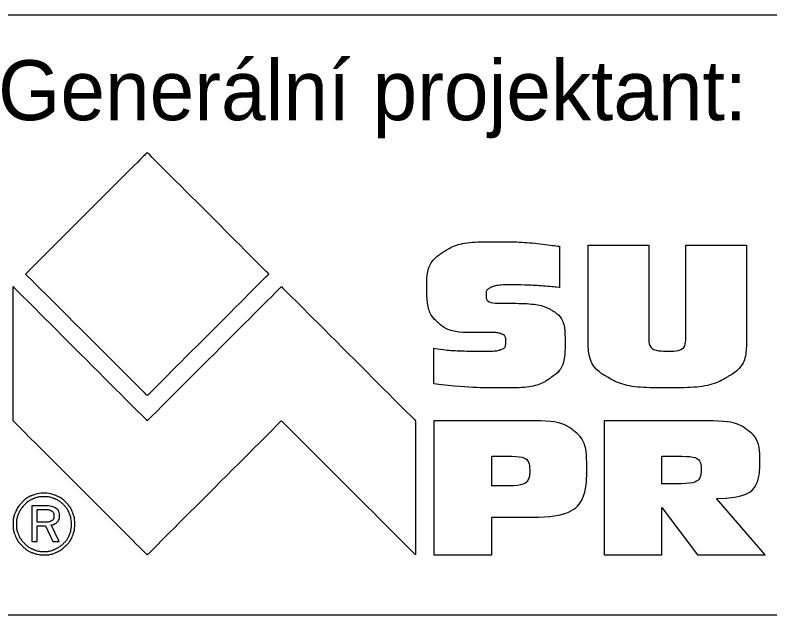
# Model space of a CAD drawing. Extents: x -573127 to 0, y -1197729 to 0.
# Drawn here: x -573104.72 to -573079.55, y -1197649.86 to -1197629.86 of the extents above; entities that cross this region are included whole.
import ezdxf

# ---------------------------------------------------------------- set-up
doc = ezdxf.new("R2010")
doc.units = 0
doc.layers.add('Default', color=7, linetype='Continuous')

msp = doc.modelspace()

# ---------------------------------------------------------------- linework, layer by layer
at = {"layer": 'Default'}
msp.add_lwpolyline([(-573106.787, -1197649.864), (-572926.787, -1197649.858), (-572926.788, -1197629.858), (-573106.788, -1197629.864)], close=True, dxfattribs=at)
msp.add_lwpolyline([(-573106.787, -1197649.864), (-572926.787, -1197649.858), (-572926.788, -1197629.858), (-573106.788, -1197629.864)], close=True, dxfattribs=at)
for points in [[(-573087.412, -1197643.389), (-573090.76, -1197643.389), (-573090.759, -1197647.863), (-573088.825, -1197647.863), (-573088.825, -1197646.607), (-573087.488, -1197646.606)], [(-573081.671, -1197643.389), (-573085.077, -1197643.389), (-573085.077, -1197647.863), (-573083.151, -1197647.863), (-573083.151, -1197646.277), (-573081.965, -1197647.863), (-573079.707, -1197647.863), (-573081.333, -1197645.976)], [(-573088.252, -1197645.561), (-573088.825, -1197645.561), (-573088.825, -1197644.572), (-573088.155, -1197644.572)], [(-573082.508, -1197645.488), (-573083.151, -1197645.488), (-573083.151, -1197644.572), (-573082.484, -1197644.572)], [(-573103.728, -1197646.225), (-573104.163, -1197646.225), (-573104.163, -1197647.41), (-573103.984, -1197647.41), (-573103.984, -1197646.89), (-573103.707, -1197646.89), (-573103.457, -1197647.41), (-573103.253, -1197647.41), (-573103.518, -1197646.864)], [(-573103.762, -1197646.772), (-573103.984, -1197646.772), (-573103.984, -1197646.346), (-573103.762, -1197646.346)]]:
    msp.add_lwpolyline(points, dxfattribs=at)
for points in [[(-573104.368, -1197638.495), (-573104.368, -1197638.495), (-573100.313, -1197634.44), (-573100.313, -1197634.44), (-573100.313, -1197634.44), (-573100.313, -1197634.44), (-573096.258, -1197638.495), (-573096.258, -1197638.495), (-573096.258, -1197638.495), (-573096.258, -1197638.495), (-573100.313, -1197642.55), (-573100.313, -1197642.55), (-573100.313, -1197642.55), (-573100.313, -1197642.55), (-573104.368, -1197638.495), (-573104.368, -1197638.495)], [(-573090.76, -1197642.162), (-573090.032, -1197642.249), (-573089.269, -1197642.293), (-573088.47, -1197642.293), (-573088.47, -1197642.293), (-573087.704, -1197642.293), (-573087.165, -1197642.18), (-573086.853, -1197641.955), (-573086.853, -1197641.955), (-573086.539, -1197641.73), (-573086.381, -1197641.342), (-573086.381, -1197640.79), (-573086.381, -1197640.79), (-573086.381, -1197640.251), (-573086.523, -1197639.891), (-573086.806, -1197639.711), (-573086.806, -1197639.711), (-573087.073, -1197639.55), (-573087.614, -1197639.469), (-573088.43, -1197639.469), (-573088.43, -1197639.469), (-573088.821, -1197639.469), (-573089.017, -1197639.377), (-573089.017, -1197639.192), (-573089.017, -1197639.192), (-573089.017, -1197639.075), (-573088.959, -1197638.99), (-573088.844, -1197638.937), (-573088.844, -1197638.937), (-573088.727, -1197638.884), (-573088.521, -1197638.858), (-573088.229, -1197638.858), (-573088.229, -1197638.858), (-573087.732, -1197638.858), (-573087.187, -1197638.886), (-573086.568, -1197638.943), (-573086.568, -1197638.943), (-573086.568, -1197638.943), (-573086.568, -1197637.571), (-573086.568, -1197637.571), (-573086.568, -1197637.571), (-573087.307, -1197637.467), (-573087.998, -1197637.416), (-573088.668, -1197637.416), (-573088.668, -1197637.416), (-573089.51, -1197637.416), (-573090.108, -1197637.535), (-573090.461, -1197637.775), (-573090.461, -1197637.775), (-573090.814, -1197638.013), (-573090.99, -1197638.393), (-573090.99, -1197638.915), (-573090.99, -1197638.915), (-573090.99, -1197639.494), (-573090.864, -1197639.896), (-573090.612, -1197640.119), (-573090.612, -1197640.119), (-573090.358, -1197640.341), (-573089.935, -1197640.451), (-573089.345, -1197640.446), (-573089.345, -1197640.446), (-573089.345, -1197640.446), (-573088.851, -1197640.446), (-573088.851, -1197640.446), (-573088.851, -1197640.446), (-573088.679, -1197640.446), (-573088.553, -1197640.465), (-573088.473, -1197640.504), (-573088.473, -1197640.504), (-573088.394, -1197640.542), (-573088.355, -1197640.625), (-573088.355, -1197640.752), (-573088.355, -1197640.752), (-573088.355, -1197640.886), (-573088.406, -1197640.972), (-573088.509, -1197641.01), (-573088.509, -1197641.01), (-573088.61, -1197641.048), (-573088.781, -1197641.067), (-573089.021, -1197641.067), (-573089.021, -1197641.067), (-573089.765, -1197641.067), (-573090.344, -1197641.034), (-573090.76, -1197640.968), (-573090.76, -1197640.968), (-573090.76, -1197640.968), (-573090.76, -1197642.162), (-573090.76, -1197642.162)], [(-573085.614, -1197640.692), (-573085.614, -1197641.263), (-573085.404, -1197641.674), (-573084.985, -1197641.923), (-573084.985, -1197641.923), (-573084.566, -1197642.169), (-573083.902, -1197642.293), (-573082.994, -1197642.293), (-573082.994, -1197642.293), (-573082.047, -1197642.293), (-573081.367, -1197642.169), (-573080.955, -1197641.922), (-573080.955, -1197641.922), (-573080.541, -1197641.676), (-573080.334, -1197641.259), (-573080.334, -1197640.672), (-573080.334, -1197640.672), (-573080.334, -1197640.672), (-573080.334, -1197637.527), (-573080.334, -1197637.527), (-573080.334, -1197637.527), (-573080.334, -1197637.527), (-573082.358, -1197637.527), (-573082.358, -1197637.527), (-573082.358, -1197637.527), (-573082.358, -1197637.527), (-573082.358, -1197640.608), (-573082.358, -1197640.608), (-573082.358, -1197640.608), (-573082.358, -1197640.913), (-573082.56, -1197641.065), (-573082.965, -1197641.065), (-573082.965, -1197641.065), (-573083.382, -1197641.065), (-573083.59, -1197640.908), (-573083.59, -1197640.596), (-573083.59, -1197640.596), (-573083.59, -1197640.596), (-573083.59, -1197637.527), (-573083.59, -1197637.527), (-573083.59, -1197637.527), (-573083.59, -1197637.527), (-573085.614, -1197637.527), (-573085.614, -1197637.527), (-573085.614, -1197637.527), (-573085.614, -1197637.527), (-573085.614, -1197640.692), (-573085.614, -1197640.692)], [(-573104.787, -1197643.389), (-573104.787, -1197643.389), (-573100.313, -1197647.864), (-573100.313, -1197647.864), (-573100.313, -1197647.864), (-573100.313, -1197647.864), (-573095.838, -1197643.389), (-573095.838, -1197643.389), (-573095.838, -1197643.389), (-573095.838, -1197643.389), (-573091.363, -1197647.863), (-573091.363, -1197647.863), (-573091.363, -1197647.863), (-573091.363, -1197647.863), (-573091.364, -1197643.389), (-573091.364, -1197643.389), (-573091.364, -1197643.389), (-573091.364, -1197643.389), (-573095.838, -1197638.915), (-573095.838, -1197638.915), (-573095.838, -1197638.915), (-573095.838, -1197638.915), (-573100.313, -1197643.389), (-573100.313, -1197643.389), (-573100.313, -1197643.389), (-573100.313, -1197643.389), (-573104.787, -1197638.915), (-573104.787, -1197638.915), (-573104.787, -1197638.915), (-573104.787, -1197638.915), (-573104.787, -1197643.389), (-573104.787, -1197643.389)], [(-573087.488, -1197646.606), (-573086.268, -1197646.606), (-573085.659, -1197646.057), (-573085.659, -1197644.959), (-573085.659, -1197644.959), (-573085.659, -1197644.371), (-573085.799, -1197643.962), (-573086.079, -1197643.733), (-573086.079, -1197643.733), (-573086.357, -1197643.503), (-573086.801, -1197643.389), (-573087.412, -1197643.389)], [(-573081.333, -1197645.976), (-573080.369, -1197645.976), (-573079.887, -1197645.555), (-573079.887, -1197644.713), (-573079.887, -1197644.713), (-573079.887, -1197644.252), (-573080.023, -1197643.916), (-573080.295, -1197643.705), (-573080.295, -1197643.705), (-573080.567, -1197643.494), (-573081.026, -1197643.389), (-573081.671, -1197643.389)], [(-573088.155, -1197644.572), (-573087.759, -1197644.572), (-573087.561, -1197644.734), (-573087.561, -1197645.058), (-573087.561, -1197645.058), (-573087.561, -1197645.394), (-573087.792, -1197645.561), (-573088.252, -1197645.561)], [(-573082.484, -1197644.572), (-573082.057, -1197644.572), (-573081.844, -1197644.712), (-573081.844, -1197644.993), (-573081.844, -1197644.993), (-573081.844, -1197645.323), (-573082.066, -1197645.488), (-573082.508, -1197645.488)], [(-573103.759, -1197645.806), (-573103.899, -1197645.806), (-573104.03, -1197645.831), (-573104.153, -1197645.881), (-573104.153, -1197645.881), (-573104.276, -1197645.932), (-573104.385, -1197646.005), (-573104.479, -1197646.102), (-573104.479, -1197646.102), (-573104.578, -1197646.202), (-573104.655, -1197646.315), (-573104.707, -1197646.442), (-573104.707, -1197646.442), (-573104.761, -1197646.569), (-573104.787, -1197646.7), (-573104.787, -1197646.834), (-573104.787, -1197646.834), (-573104.787, -1197646.972), (-573104.761, -1197647.102), (-573104.71, -1197647.227), (-573104.71, -1197647.227), (-573104.658, -1197647.351), (-573104.583, -1197647.462), (-573104.485, -1197647.559), (-573104.485, -1197647.559), (-573104.387, -1197647.658), (-573104.276, -1197647.734), (-573104.152, -1197647.786), (-573104.152, -1197647.786), (-573104.096, -1197647.809), (-573104.038, -1197647.828), (-573103.979, -1197647.84)], [(-573103.979, -1197647.84), (-573103.908, -1197647.856), (-573103.835, -1197647.864), (-573103.759, -1197647.864), (-573103.759, -1197647.864), (-573103.623, -1197647.864), (-573103.492, -1197647.837), (-573103.366, -1197647.784), (-573103.366, -1197647.784), (-573103.239, -1197647.732), (-573103.126, -1197647.655), (-573103.025, -1197647.556), (-573103.025, -1197647.556), (-573102.928, -1197647.461), (-573102.854, -1197647.352), (-573102.804, -1197647.229), (-573102.804, -1197647.229), (-573102.754, -1197647.107), (-573102.729, -1197646.975), (-573102.729, -1197646.834), (-573102.729, -1197646.834), (-573102.729, -1197646.695), (-573102.754, -1197646.563), (-573102.806, -1197646.438), (-573102.806, -1197646.438), (-573102.856, -1197646.313), (-573102.93, -1197646.203), (-573103.025, -1197646.107), (-573103.025, -1197646.107), (-573103.122, -1197646.009), (-573103.233, -1197645.934), (-573103.358, -1197645.883), (-573103.358, -1197645.883), (-573103.483, -1197645.831), (-573103.617, -1197645.806), (-573103.759, -1197645.806)], [(-573102.841, -1197646.839), (-573102.841, -1197646.965), (-573102.863, -1197647.082), (-573102.908, -1197647.19), (-573102.908, -1197647.19), (-573102.952, -1197647.298), (-573103.017, -1197647.394), (-573103.103, -1197647.477), (-573103.103, -1197647.477), (-573103.193, -1197647.565), (-573103.294, -1197647.632), (-573103.407, -1197647.679), (-573103.407, -1197647.679), (-573103.52, -1197647.725), (-573103.637, -1197647.749), (-573103.759, -1197647.749), (-573103.759, -1197647.749), (-573103.88, -1197647.749), (-573103.996, -1197647.726), (-573104.107, -1197647.679), (-573104.107, -1197647.679), (-573104.217, -1197647.633), (-573104.317, -1197647.567), (-573104.405, -1197647.48), (-573104.405, -1197647.48), (-573104.492, -1197647.392), (-573104.559, -1197647.293), (-573104.605, -1197647.182), (-573104.605, -1197647.182), (-573104.652, -1197647.072), (-573104.675, -1197646.957), (-573104.675, -1197646.836), (-573104.675, -1197646.836), (-573104.675, -1197646.716), (-573104.651, -1197646.599), (-573104.604, -1197646.487), (-573104.604, -1197646.487), (-573104.556, -1197646.376), (-573104.488, -1197646.275), (-573104.399, -1197646.184), (-573104.399, -1197646.184), (-573104.313, -1197646.098), (-573104.215, -1197646.033), (-573104.106, -1197645.987), (-573104.106, -1197645.987), (-573103.997, -1197645.943), (-573103.881, -1197645.921), (-573103.759, -1197645.921), (-573103.759, -1197645.921), (-573103.634, -1197645.921), (-573103.515, -1197645.943), (-573103.403, -1197645.99), (-573103.403, -1197645.99), (-573103.291, -1197646.036), (-573103.191, -1197646.103), (-573103.103, -1197646.19), (-573103.103, -1197646.19), (-573103.018, -1197646.275), (-573102.953, -1197646.373), (-573102.909, -1197646.484), (-573102.909, -1197646.484), (-573102.864, -1197646.595), (-573102.841, -1197646.714), (-573102.841, -1197646.839)], [(-573103.762, -1197646.346), (-573103.642, -1197646.346), (-573103.556, -1197646.363), (-573103.502, -1197646.397), (-573103.502, -1197646.397), (-573103.449, -1197646.431), (-573103.422, -1197646.487), (-573103.422, -1197646.565), (-573103.422, -1197646.565), (-573103.422, -1197646.64), (-573103.448, -1197646.693), (-573103.498, -1197646.725), (-573103.498, -1197646.725), (-573103.549, -1197646.756), (-573103.637, -1197646.772), (-573103.762, -1197646.772)], [(-573103.518, -1197646.864), (-573103.432, -1197646.852), (-573103.365, -1197646.818), (-573103.314, -1197646.762), (-573103.314, -1197646.762), (-573103.263, -1197646.705), (-573103.238, -1197646.636), (-573103.238, -1197646.553), (-573103.238, -1197646.553), (-573103.238, -1197646.441), (-573103.278, -1197646.358), (-573103.358, -1197646.305), (-573103.358, -1197646.305), (-573103.438, -1197646.252), (-573103.562, -1197646.225), (-573103.728, -1197646.225)]]:
    msp.add_open_spline(points, degree=3, dxfattribs=at)

# ---------------------------------------------------------------- texts
msp.add_text('Generální projektant:', height=2, rotation=0.0018, dxfattribs=at).set_placement((-573105.287, -1197633.364))

doc.saveas('drawing.dxf')
